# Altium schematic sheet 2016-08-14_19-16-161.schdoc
size 478 x 220 mm; SheetNumber: 1; SheetTotal: 1
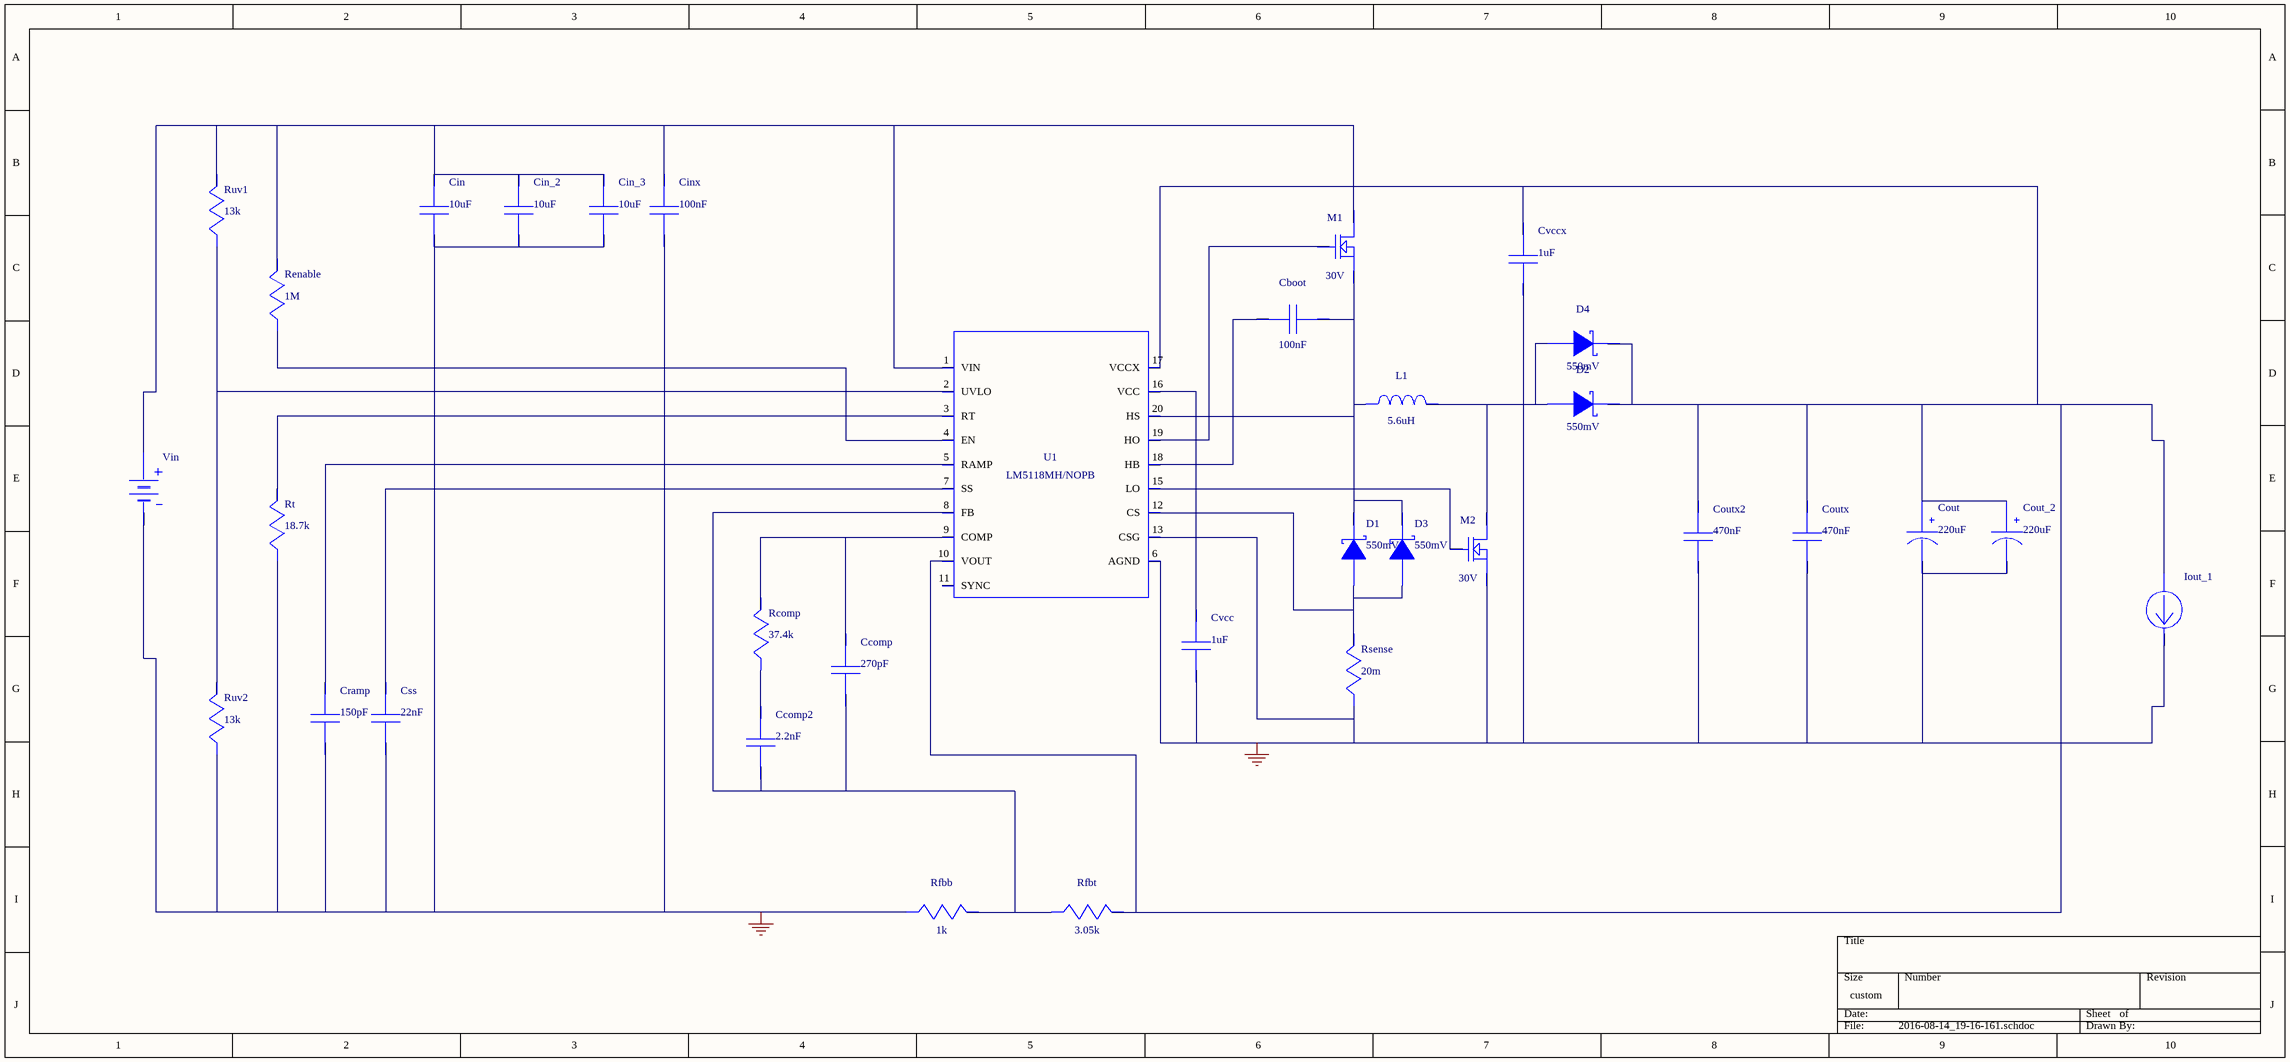
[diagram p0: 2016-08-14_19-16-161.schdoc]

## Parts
Cboot  value 100nF  (hidden comment: GRM21BR71E104KA01L)
Ccomp  value 270pF  (hidden comment: CC0805KRX7R9BB271)
Ccomp2  value 2.2nF  (hidden comment: CC0805KRX7R9BB222)
Cin  value 10uF  (hidden comment: GRM21BR61C106KE15L)
Cin_2  value 10uF  (hidden comment: GRM21BR61C106KE15L)
Cin_3  value 10uF  (hidden comment: GRM21BR61C106KE15L)
Cinx  value 100nF  (hidden comment: 08053C104KAT2A)
Cout  value 220uF  (hidden comment: APXE6R3ARA221MF61G)
Cout_2  value 220uF  (hidden comment: APXE6R3ARA221MF61G)
Coutx  value 470nF  (hidden comment: GRM188R71C474KA88D)
Coutx2  value 470nF  (hidden comment: GRM188R71C474KA88D)
Cramp  value 150pF  (hidden comment: C2012C0G1H151J)
Css  value 22nF  (hidden comment: CC0805KRX7R9BB223)
Cvcc  value 1uF  (hidden comment: EMK212B7105KG-T)
Cvccx  value 1uF  (hidden comment: C1005X5R0J105M)
D1  value 550mV  (hidden comment: B540C-13-F)
D2  value 550mV  (hidden comment: B540C-13-F)
D3  value 550mV  (hidden comment: B540C-13-F)
D4  value 550mV  (hidden comment: B540C-13-F)
Iout_1  WB_CURRENT_LOAD  (value not drawn)
L1  value 5.6uH  (hidden comment: SDR1307-5R6ML)
M1  value 30V  (hidden comment: CSD17579Q3A)
M2  value 30V  (hidden comment: CSD17579Q3A)
Rcomp  value 37.4k  (hidden comment: CRCW040237K4FKED)
Renable  value 1M  (hidden comment: CRCW04021M00FKED)
Rfbb  value 1k  (hidden comment: CRCW04021K00FKED)
Rfbt  value 3.05k  (hidden comment: RT0805BRD073K05L)
Rsense  value 20m  (hidden comment: PRL1632-R020-F-T1)
Rt  value 18.7k  (hidden comment: CRCW040218K7FKED)
Ruv1  value 13k  (hidden comment: CRCW040213K0FKED)
Ruv2  value 13k  (hidden comment: CRCW040213K0FKED)
U1  LM5118MH/NOPB
Vin  WB_BATTERY  (value not drawn)

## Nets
0: Cin.2 Cin_2.2 Cin_3.2 Cinx.2 Cout.2(-) Cout_2.2(-) Coutx.2 Coutx2.2 Cramp.2 Css.2 Cvcc.2 Cvccx.1 Iout_1.2(-) M2.1(Source) M2.2(Source) M2.3(Source) Rfbb.2 Rsense.2 Rt.2 Ruv2.2 U1.6(AGND) U1.13(CSG) U1.14(PGND) U1.21(EP) Vin.2(-)
NetCboot_1: Cboot.1 D1.1(K) D3.1(K) L1.2 M1.1(Source) M1.2(Source) M1.3(Source) U1.20(HS)
NetCboot_2: Cboot.2 U1.18(HB)
NetCcomp2_1: Ccomp2.1 Rcomp.2
NetCcomp_1: Ccomp.1 Rcomp.1 U1.9(COMP)
NetCcomp_2: Ccomp.2 Ccomp2.2 Rfbb.1 Rfbt.2 U1.8(FB)
NetCin_1: Cin.1 Cin_2.1 Cin_3.1 Cinx.1 M1.5(Drain) M1.6(Drain) M1.7(Drain) M1.8(Drain) M1.9(Drain) Renable.1 Ruv1.1 U1.1(VIN) Vin.1(+)
NetCout_1: Cout.1(+) Cout_2.1(+) Coutx.1 Coutx2.1 Cvccx.2 D2.1(K) D4.1(K) Iout_1.1(+) Rfbt.1 U1.10(VOUT) U1.17(VCCX)
NetCramp_1: Cramp.1 U1.5(RAMP)
NetCss_1: Css.1 U1.7(SS)
NetCvcc_1: Cvcc.1 U1.16(VCC)
NetD1_2: D1.2(A) D3.2(A) Rsense.1 U1.12(CS)
NetD2_2: D2.2(A) D4.2(A) L1.1 M2.5(Drain) M2.6(Drain) M2.7(Drain) M2.8(Drain) M2.9(Drain)
NetM1_4: M1.4(Gate) U1.19(HO)
NetM2_4: M2.4(Gate) U1.15(LO)
NetRenable_2: Renable.2 U1.4(EN)
NetRt_1: Rt.1 U1.3(RT)
NetRuv1_2: Ruv1.2 Ruv2.1 U1.2(UVLO)

Not connected (* = marked no-connect by the designer): U1 11(SYNC)

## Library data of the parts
Cboot = GRM21BR71E104KA01L: GRM21BR71E104KA0; Manufacturer Name: MuRata
Ccomp = CC0805KRX7R9BB271: CC0805KRX7R9BB27; Manufacturer Name: Yageo America
Ccomp2 = CC0805KRX7R9BB222: CC0805KRX7R9BB22; Manufacturer Name: Yageo America
Cin Cin_2 Cin_3 = GRM21BR61C106KE15L: GRM21BR61C106KE1; Manufacturer Name: MuRata
Cinx = 08053C104KAT2A: Manufacturer Name: AVX
Cout Cout_2 = APXE6R3ARA221MF61G: APXE6R3ARA221MF6; Manufacturer Name: Chemi-Con
Coutx Coutx2 = GRM188R71C474KA88D: GRM188R71C474KA8; Manufacturer Name: MuRata
Cramp = C2012C0G1H151J: Manufacturer Name: TDK
Css = CC0805KRX7R9BB223: CC0805KRX7R9BB00; Manufacturer Name: Yageo America
Cvcc = EMK212B7105KG-T: Manufacturer Name: Taiyo Yuden
Cvccx = C1005X5R0J105M: Manufacturer Name: TDK
D1-D4 = B540C-13-F: Manufacturer Name: Diodes Inc.
L1 = SDR1307-5R6ML: Manufacturer Name: Bourns
M1 M2 = CSD17579Q3A: Manufacturer Name: Texas Instruments
Rcomp = CRCW040237K4FKED: Manufacturer Name: Vishay-Dale
Renable = CRCW04021M00FKED: Manufacturer Name: Vishay-Dale
Rfbb = CRCW04021K00FKED: Manufacturer Name: Vishay-Dale
Rfbt = RT0805BRD073K05L: Manufacturer Name: Yageo America
Rsense = PRL1632-R020-F-T1: PRL1632-R020-F-T; Manufacturer Name: Susumu Co Ltd
Rt = CRCW040218K7FKED: Manufacturer Name: Vishay-Dale
Ruv1 Ruv2 = CRCW040213K0FKED: Manufacturer Name: Vishay-Dale
U1 = LM5118MH/NOPB: Manufacturer Name: Texas Instruments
